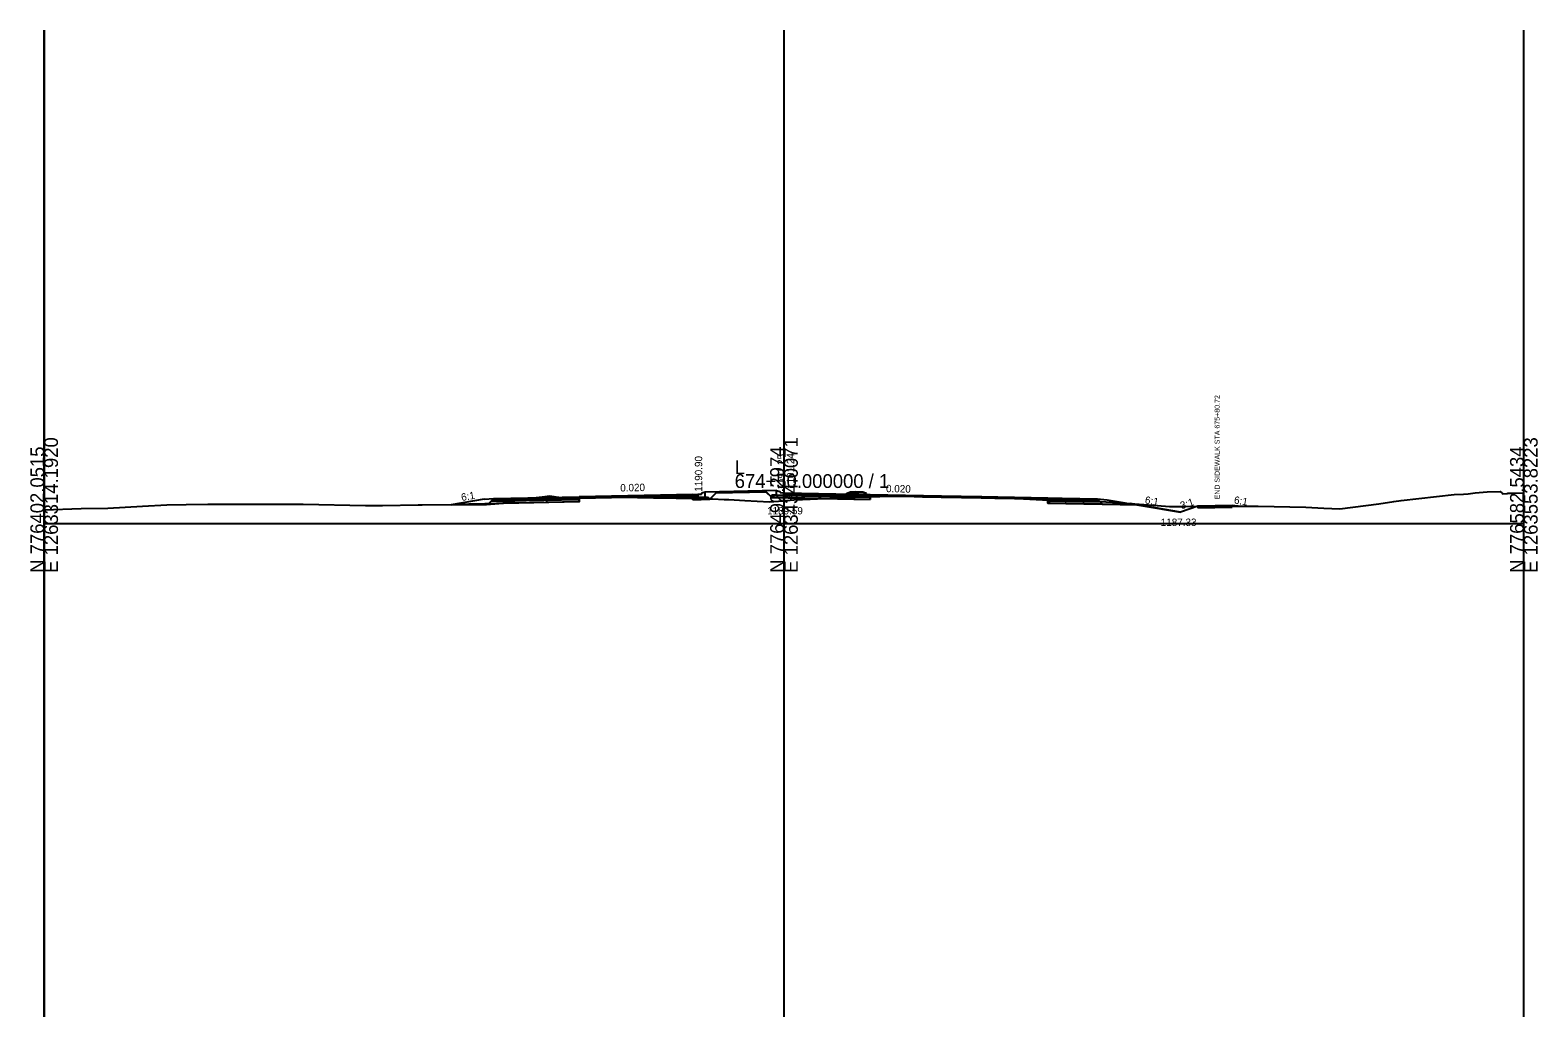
# Model space of a CAD drawing. Extents: x -41 to 1262860, y -100 to 777489.
# Drawn here: x 497.2 to 802.8, y 760 to 960 of the extents above; entities that cross this region are included whole.
import ezdxf

# ---------------------------------------------------------------- set-up
doc = ezdxf.new("R2010")
doc.units = 0
for name, color, linetype in [('Exist Cross Section Cell', 7, 'Continuous'), ('Exist XS Center Line Elevation Label', 7, 'Continuous'), ('Exist XS Ground Line', 7, 'Continuous'), ('Prop CMT Pvmt Concrete', 7, 'Continuous'), ('Prop CMT Pvmt Course 1', 7, 'Continuous'), ('Prop CMT Pvmt Course 4', 7, 'Continuous'), ('Prop CMT Pvmt Surface', 7, 'Continuous'), ('Prop CMT Shld Paved Course 1', 7, 'Continuous'), ('Prop CMT Shld Paved Course 2', 7, 'Continuous'), ('Prop CMT Shld Paved Course 4', 7, 'Continuous'), ('Prop CMT Subgrade Earthwork', 7, 'Continuous'), ('Prop Conc Curb and Gutter', 7, 'Continuous'), ('Prop Conc Island Cover', 7, 'Continuous'), ('Prop XS Ditch Standard Text', 7, 'Continuous'), ('Prop XS Earthwork Shape', 7, 'Continuous'), ('Prop XS Elevation Labels', 7, 'Continuous'), ('Prop XS Exc Vertical Line 1', 7, 'Continuous'), ('Prop XS Exc Vertical Line 2', 7, 'Continuous'), ('Prop XS Exc Vertical Line 3', 7, 'Continuous'), ('Prop XS Finish Grade', 7, 'Continuous'), ('Prop XS Hydro Elevations', 7, 'Continuous'), ('Prop XS SE Text', 7, 'Continuous'), ('Prop XS Side Slope Text', 7, 'Continuous'), ('Scratch_Level_4', 7, 'Continuous'), ('Scratch_Level_6', 7, 'Continuous')]:
    doc.layers.add(name, color=color, linetype=linetype)

msp = doc.modelspace()

# ---------------------------------------------------------------- linework, layer by layer
at = {"layer": 'Exist Cross Section Cell'}
for p, q in [((650, 860), (650, 870)), ((500, 860), (650, 860)), ((650, 860), (800, 860))]:
    msp.add_line(p, q, dxfattribs=at)
at = {"layer": 'Exist XS Ground Line'}
msp.add_lwpolyline([(500, 862.79), (500.03, 862.79), (507.53, 863.01), (512.9, 863.13), (519.95, 863.5), (524.84, 863.75), (528.77, 863.87), (533.18, 863.92), (548.07, 863.95), (551.09, 863.9), (552.54, 863.9), (565.18, 863.68), (568.59, 863.62), (575.86, 863.75), (576.53, 863.76), (576.56, 863.76), (576.67, 863.76), (587.02, 863.82), (589.67, 863.84), (592.15, 864.07), (597.43, 864.93), (598.99, 865.17), (600.42, 865.36), (602.55, 865.6), (604.31, 865.33), (606.22, 864.85), (607.18, 865.08), (608.05, 865.15), (611.41, 865.3), (617.02, 865.31), (623.51, 865.22), (628.16, 865.12), (635.49, 864.98), (637.87, 864.89), (638.84, 864.85), (642.05, 864.65), (647.05, 864.42), (649.74, 864.57), (652, 864.77), (653.51, 864.88), (653.77, 864.89), (664.41, 865.33), (666.01, 865.39), (676.36, 865.62), (678.08, 865.66), (679.35, 865.64), (690.13, 865.46), (692.72, 865.32), (693.38, 865.28), (703.7, 864.7), (705.7, 864.63), (705.97, 864.62), (706.83, 864.58), (708.7, 864.57), (711.21, 864.61), (716.59, 864.3), (725.66, 863.62), (728.13, 863.42), (731.4, 863.45), (736.16, 863.53), (746.13, 863.52), (755.78, 863.3), (759.44, 863.11), (762.68, 862.96), (770.61, 864), (773.62, 864.46), (775.16, 864.67), (785.9, 865.85), (787.78, 865.94), (788.72, 866.04), (790.11, 866.21), (792.59, 866.4), (795.17, 866.52), (795.59, 866.12), (795.67, 866.04), (796.62, 866.1), (796.77, 866.12), (797.92, 866.16), (800, 866.22)], dxfattribs=at)
at = {"layer": 'Prop CMT Pvmt Concrete'}
for p, q in [((733.89, 863.49), (740.85, 863.63)), ((733.89, 863.49), (733.89, 863.16)), ((733.89, 863.16), (740.85, 863.3)), ((740.85, 863.63), (740.85, 863.3))]:
    msp.add_line(p, q, dxfattribs=at)
at = {"layer": 'Prop CMT Pvmt Course 1'}
for p, q in [((631.5, 865.87), (632.5, 865.89)), ((631.5, 865.62), (632.5, 865.64)), ((632.5, 865.64), (632.5, 865.89)), ((650, 866.24), (650, 865.99))]:
    msp.add_line(p, q, dxfattribs=at)
for points in [[(608.5, 865.41), (608.5, 865.16), (631.5, 865.62), (631.5, 865.62), (631.5, 865.87), (631.5, 865.87), (631.5, 865.87), (608.5, 865.41), (608.5, 865.41)], [(703.5, 865.17), (703.5, 864.92), (689.99, 865.19), (689.99, 865.19), (689.99, 865.19), (681.96, 865.35), (681.85, 865.35), (681.85, 865.35), (667.5, 865.64), (667.5, 865.64), (667.5, 865.89), (667.5, 865.89), (667.5, 865.89), (681.85, 865.6), (681.85, 865.6), (681.96, 865.6), (689.99, 865.44), (689.99, 865.44), (689.99, 865.44), (703.5, 865.17), (703.5, 865.17)]]:
    msp.add_lwpolyline(points, dxfattribs=at)
at = {"layer": 'Prop CMT Pvmt Course 4'}
for p, q in [((631.5, 864.83), (631.5, 865.29)), ((667.5, 864.85), (667.5, 865.42)), ((590.58, 864.47), (590.11, 864)), ((608.5, 864.37), (590.11, 864)), ((631.5, 864.83), (634.95, 864.9))]:
    msp.add_line(p, q, dxfattribs=at)
msp.add_lwpolyline([(647.55, 865.25), (667.5, 864.85)], dxfattribs=at)
at = {"layer": 'Prop CMT Pvmt Surface'}
for p, q in [((591.18, 865.06), (608.5, 865.41)), ((608.5, 865.41), (631.5, 865.87)), ((631.5, 865.87), (632.5, 865.89)), ((650, 866.24), (667.5, 865.89)), ((667.5, 865.89), (713.5, 864.97))]:
    msp.add_line(p, q, dxfattribs=at)
at = {"layer": 'Prop CMT Shld Paved Course 1'}
for p, q in [((608.5, 865.16), (590.92, 864.81)), ((601.89, 865.03), (601.89, 865.28)), ((604.5, 865.33), (604.5, 865.33)), ((608.5, 865.41), (608.5, 865.16)), ((608.5, 865.16), (608.5, 865.16)), ((703.73, 865.16), (703.73, 864.91)), ((707.73, 865.08), (707.73, 865.08)), ((591.18, 865.06), (590.92, 864.81)), ((703.5, 864.92), (713.76, 864.71)), ((703.73, 864.91), (703.73, 864.91)), ((713.76, 864.71), (713.5, 864.97))]:
    msp.add_line(p, q, dxfattribs=at)
for points in [[(650, 866.24), (650, 866.24), (667.5, 865.89)], [(650, 865.99), (650, 865.99), (667.5, 865.64)]]:
    msp.add_lwpolyline(points, dxfattribs=at)
at = {"layer": 'Prop CMT Shld Paved Course 2'}
for p, q in [((608.5, 865.16), (611.41, 865.22)), ((611.41, 865.22), (608.5, 865.16)), ((608.5, 865.16), (608.5, 864.83)), ((617.02, 865.33), (611.41, 865.22)), ((611.41, 865.22), (616.04, 865.31)), ((611.41, 865.22), (611.41, 865.22)), ((611.41, 865.22), (611.41, 865.22)), ((611.41, 865.22), (611.41, 865.22)), ((611.41, 865.22), (611.41, 865.22)), ((611.41, 865.22), (611.41, 865.22)), ((616.04, 865.31), (616.04, 865.31)), ((616.04, 865.31), (616.04, 865.31)), ((616.04, 865.31), (617.02, 865.31)), ((623.51, 865.46), (617.02, 865.33)), ((617.02, 865.33), (617.02, 865.33)), ((617.02, 865.31), (617.02, 865.31)), ((617.02, 865.31), (623.51, 865.22)), ((628.16, 865.55), (623.51, 865.46)), ((623.51, 865.22), (625.85, 865.17)), ((625.85, 865.17), (628.16, 865.22)), ((625.85, 865.17), (625.85, 865.17)), ((631.5, 865.62), (628.16, 865.55)), ((628.16, 865.55), (628.16, 865.55)), ((628.16, 865.22), (631.5, 865.29)), ((628.16, 865.22), (628.16, 865.22)), ((631.5, 865.29), (631.5, 865.62)), ((631.5, 865.62), (631.5, 865.62)), ((631.5, 865.62), (631.5, 865.62)), ((631.5, 865.29), (631.5, 865.29)), ((631.51, 865.29), (632.5, 865.31)), ((632.5, 865.64), (632.5, 865.31)), ((650, 865.66), (650, 865.99)), ((667.5, 865.42), (667.5, 865.64)), ((667.5, 865.64), (667.5, 865.64)), ((667.5, 865.64), (667.5, 865.64)), ((667.5, 865.64), (676.36, 865.46)), ((672.58, 865.54), (667.5, 865.42)), ((667.5, 865.42), (667.5, 865.42)), ((676.36, 865.46), (672.58, 865.54)), ((672.58, 865.54), (672.58, 865.54)), ((678.08, 865.43), (676.36, 865.46)), ((676.36, 865.46), (676.36, 865.46)), ((676.36, 865.46), (676.36, 865.46)), ((676.36, 865.46), (678.08, 865.43)), ((679.35, 865.4), (678.08, 865.43)), ((678.08, 865.43), (679.35, 865.4)), ((681.85, 865.35), (679.35, 865.4)), ((679.35, 865.4), (679.35, 865.4)), ((679.35, 865.4), (679.35, 865.4)), ((679.35, 865.4), (681.85, 865.35)), ((681.96, 865.35), (681.85, 865.35)), ((681.85, 865.35), (681.96, 865.35)), ((689.99, 865.19), (681.96, 865.35)), ((681.96, 865.35), (681.96, 865.35)), ((681.96, 865.35), (681.96, 865.35)), ((681.96, 865.35), (689.99, 865.19)), ((690.13, 865.19), (689.99, 865.19)), ((689.99, 865.19), (689.99, 865.19)), ((689.99, 865.19), (689.99, 865.19)), ((689.99, 865.19), (690.13, 865.19)), ((692.72, 865.13), (690.13, 865.19)), ((690.13, 865.19), (690.13, 865.19)), ((690.13, 865.19), (690.13, 865.19)), ((690.13, 865.19), (692.72, 865.13)), ((693.38, 865.12), (692.72, 865.13)), ((692.72, 865.13), (692.72, 865.13)), ((692.72, 865.13), (692.72, 865.13)), ((692.72, 865.13), (693.38, 865.12)), ((697.79, 865.03), (693.38, 865.12)), ((693.38, 865.12), (693.38, 865.12)), ((693.38, 865.12), (693.38, 865.12)), ((693.38, 865.12), (693.38, 865.12)), ((693.38, 865.12), (693.38, 865.12)), ((693.38, 865.12), (703.5, 864.92)), ((608.5, 864.83), (590.58, 864.47)), ((590.58, 864.47), (590.92, 864.81)), ((601.89, 864.69), (601.89, 865.03)), ((603.9, 864.73), (603.9, 864.73)), ((603.9, 864.73), (603.9, 864.73)), ((608.5, 864.83), (608.5, 864.83)), ((703.5, 864.71), (697.79, 865.03)), ((697.79, 865.03), (697.79, 865.03)), ((697.79, 865.03), (697.79, 865.03)), ((703.5, 864.92), (703.5, 864.92)), ((703.5, 864.92), (703.5, 864.92)), ((703.5, 864.92), (703.5, 864.92)), ((703.5, 864.92), (703.5, 864.71)), ((703.5, 864.59), (703.5, 864.71)), ((703.5, 864.71), (703.5, 864.71)), ((703.5, 864.71), (703.5, 864.71)), ((703.5, 864.59), (714.1, 864.37)), ((703.73, 864.91), (703.73, 864.58)), ((703.73, 864.58), (703.73, 864.58)), ((714.1, 864.37), (713.76, 864.71))]:
    msp.add_line(p, q, dxfattribs=at)
msp.add_lwpolyline([(650, 865.66), (667.5, 865.31)], dxfattribs=at)
at = {"layer": 'Prop CMT Shld Paved Course 4'}
for p, q in [((625.85, 865.17), (628.16, 865.12)), ((628.16, 865.12), (631.5, 865.06)), ((632.5, 865.31), (634.5, 865.35)), ((634.5, 865.35), (634.95, 864.9)), ((648, 865.7), (647.55, 865.25)), ((650, 865.66), (648, 865.7)), ((601.89, 864.23), (601.89, 864.69)), ((603.9, 864.73), (603.9, 864.73)), ((608.5, 864.83), (608.5, 864.37)), ((703.5, 864.59), (703.5, 864.13)), ((703.73, 864.58), (703.73, 864.12)), ((703.73, 864.12), (714.8, 863.9)), ((714.56, 863.91), (714.1, 864.37))]:
    msp.add_line(p, q, dxfattribs=at)
at = {"layer": 'Prop CMT Subgrade Earthwork'}
for p, q in [((608.5, 864.37), (608.5, 865.17)), ((634.95, 864.9), (636.45, 866.39)), ((647.55, 865.25), (646.17, 866.63)), ((667.5, 864.85), (647.55, 865.25)), ((667.5, 865.42), (667.5, 864.85)), ((608.5, 864.37), (582.89, 863.85)), ((631.5, 864.83), (631.5, 865.06)), ((634.95, 864.9), (631.5, 864.83)), ((703.5, 864.13), (703.5, 864.71)), ((703.5, 864.13), (721.78, 863.76))]:
    msp.add_line(p, q, dxfattribs=at)
at = {"layer": 'Prop Conc Curb and Gutter'}
for p, q in [((633.19, 865.9), (632.5, 865.89)), ((632.5, 865.89), (632.5, 865.31)), ((632.5, 865.31), (634, 865.34)), ((633.25, 865.98), (633.25, 865.96)), ((634, 866.34), (633.35, 866.12)), ((634, 865.34), (634, 866.34)), ((634, 865.34), (634, 865.34)), ((648.5, 866.69), (649.15, 866.47)), ((648.5, 865.69), (648.5, 866.69)), ((650, 865.66), (648.5, 865.69)), ((649.25, 866.33), (649.25, 866.31)), ((649.31, 866.25), (650, 866.24)), ((650, 865.66), (650, 866.24)), ((662.75, 865.98), (662.76, 866.15)), ((662.75, 865.98), (662.75, 865.98)), ((662.75, 865.98), (662.75, 865.86)), ((664.51, 865.98), (662.75, 865.98)), ((662.75, 865.98), (662.75, 865.98)), ((662.75, 865.86), (662.75, 865.86)), ((662.75, 865.86), (664.51, 865.86)), ((662.76, 866.15), (663.51, 866.4)), ((662.76, 866.15), (662.76, 866.15)), ((663.51, 866.4), (664.51, 866.42)), ((663.51, 866.4), (663.51, 866.4)), ((664.51, 866.42), (664.51, 865.98)), ((664.51, 865.86), (664.51, 865.98)), ((664.51, 865.98), (664.51, 865.98)), ((664.51, 865.86), (664.51, 865.86)), ((664.51, 865.86), (664.51, 865.86)), ((665.99, 866.32), (664.99, 866.34)), ((664.99, 866.34), (664.99, 865.9)), ((666.75, 865.9), (664.99, 865.9)), ((664.99, 865.9), (664.99, 865.78)), ((664.99, 865.9), (664.99, 865.9)), ((664.99, 865.78), (664.99, 865.78)), ((664.99, 865.78), (666.75, 865.78)), ((666.74, 866.07), (665.99, 866.32)), ((665.99, 866.32), (665.99, 866.32)), ((666.75, 865.9), (666.74, 866.07)), ((666.74, 866.07), (666.74, 866.07)), ((666.75, 865.78), (666.75, 865.9)), ((666.75, 865.9), (666.75, 865.9)), ((666.75, 865.9), (666.75, 865.9)), ((666.75, 865.78), (666.75, 865.78)), ((666.75, 865.78), (666.75, 865.78))]:
    msp.add_line(p, q, dxfattribs=at)
for centre, radius, start, end in [((633.19, 865.96), 0.0625, 271.1458, 360), ((633.4, 865.98), 0.146, 108.435, 180), ((649.1, 866.33), 0.146, 0, 71.565), ((649.31, 866.31), 0.0625, 180, 268.8542)]:
    msp.add_arc(centre, radius, start, end, dxfattribs=at)
at = {"layer": 'Prop Conc Island Cover'}
for p, q in [((648.5, 866.69), (634, 866.34)), ((634, 866.07), (634, 866.07)), ((664.51, 866.42), (664.51, 866.17)), ((664.99, 866.34), (664.51, 866.42)), ((664.99, 866.09), (664.51, 866.17)), ((664.99, 866.09), (664.99, 866.34)), ((664.99, 866.34), (664.99, 866.34)), ((664.99, 866.09), (664.99, 866.09))]:
    msp.add_line(p, q, dxfattribs=at)
at = {"layer": 'Prop XS Earthwork Shape'}
for points in [[(602.55, 865.6), (604.31, 865.33), (606.22, 864.85), (607.18, 865.08), (608.05, 865.15), (608.5, 865.17), (608.5, 864.37), (591.7, 864.03), (592.15, 864.07), (597.43, 864.93), (598.99, 865.17), (600.42, 865.36)], [(637.87, 864.89), (638.84, 864.85), (642.05, 864.65), (647.05, 864.42), (649.74, 864.57), (652, 864.77), (653.51, 864.88), (653.77, 864.89), (657.55, 865.05), (647.55, 865.25), (646.41, 866.38), (636.19, 866.14), (635.04, 864.99), (635.49, 864.98)], [(667.5, 864.85), (657.55, 865.05), (664.41, 865.33), (666.01, 865.39), (667.5, 865.42)], [(582.52, 863.79), (587.02, 863.82), (589.67, 863.84), (591.7, 864.03), (590.11, 864), (582.89, 863.85)], [(631.5, 864.83), (631.5, 865.06), (635.04, 864.99), (634.95, 864.9)], [(705.7, 864.63), (705.97, 864.62), (706.83, 864.58), (708.7, 864.57), (711.21, 864.61), (714.02, 864.45), (714.56, 863.91), (703.5, 864.13), (703.5, 864.71), (703.7, 864.7)], [(714.02, 864.45), (716.59, 864.3), (720.15, 864.03), (721.78, 863.76), (714.56, 863.91)], [(733.89, 863.49), (730.39, 862.33), (721.78, 863.76), (720.15, 864.03), (725.66, 863.62), (728.13, 863.42), (731.4, 863.45)], [(740.85, 863.63), (741.35, 863.64), (742.05, 863.52), (736.16, 863.53), (733.89, 863.49)]]:
    msp.add_lwpolyline(points, close=True, dxfattribs=at)
at = {"layer": 'Prop XS Exc Vertical Line 1'}
msp.add_line((500, 760), (500, 960), dxfattribs=at)
at = {"layer": 'Prop XS Exc Vertical Line 2'}
msp.add_line((650, 760), (650, 960), dxfattribs=at)
at = {"layer": 'Prop XS Exc Vertical Line 3'}
msp.add_line((800, 760), (800, 960), dxfattribs=at)
at = {"layer": 'Prop XS Finish Grade'}
for p, q in [((589.18, 864.9), (582.52, 863.79)), ((589.18, 864.9), (591.18, 865.06)), ((591.18, 865.06), (590.11, 864)), ((713.5, 864.97), (715.5, 864.81)), ((713.5, 864.97), (714.56, 863.91)), ((715.5, 864.81), (730.39, 862.33)), ((733.89, 863.49), (730.39, 862.33)), ((740.85, 863.63), (733.89, 863.49)), ((740.85, 863.63), (741.35, 863.64)), ((741.35, 863.64), (742.05, 863.52))]:
    msp.add_line(p, q, dxfattribs=at)
at = {"layer": 'Scratch_Level_4'}
msp.add_line((800, 760), (800, 960), dxfattribs=at)
at = {"layer": 'Scratch_Level_6'}
msp.add_line((500, 960), (500, 760), dxfattribs=at)

# ---------------------------------------------------------------- texts
at = {"layer": 'Exist Cross Section Cell'}
for s, p in [('E 1263314.1920', (502.8, 850)), ('E 1263553.8223', (802.8, 850)), ('N 776402.0515', (500, 850)), ('N 776492.2974', (650, 850)), ('E 1263434.0071', (652.8, 850)), ('N 776582.5434', (800, 850))]:
    msp.add_text(s, height=2.8, rotation=90, dxfattribs=at).set_placement(p)
for s, p in [('L', (640, 870)), ('674+50.000000 / 1', (640, 867.2))]:
    msp.add_text(s, height=2.8, dxfattribs=at).set_placement(p)
at = {"layer": 'Exist XS Center Line Elevation Label'}
msp.add_text('1189.59', height=1.5, dxfattribs=at).set_placement((646.57, 861.84))
at = {"layer": 'Prop XS Ditch Standard Text'}
msp.add_text('1187.33', height=1.5, dxfattribs=at).set_placement((726.38, 859.5))
at = {"layer": 'Prop XS Elevation Labels'}
for s, p in [('1190.90', (633.42, 866.43)), ('1191.25', (650.18, 866.85))]:
    msp.add_text(s, height=1.5, rotation=90, dxfattribs=at).set_placement(p)
at = {"layer": 'Prop XS Hydro Elevations'}
for s, height, p in [('END SIDEWALK STA 675+80.72', 1.0331, (738.34, 864.89)), ('1191.24', 1.5, (652.07, 867.01))]:
    msp.add_text(s, height=height, rotation=90, dxfattribs=at).set_placement(p)
at = {"layer": 'Prop XS SE Text'}
for rotation, p in [(1.1458, (616.81, 866.48)), (358.8542, (670.67, 866.35))]:
    msp.add_text('0.020', height=1.5, rotation=rotation, dxfattribs=at).set_placement(p)
at = {"layer": 'Prop XS Side Slope Text'}
for s, rotation, p in [('6:1', 9.4623, (584.67, 864.56)), ('6:1', 350.5377, (723.09, 864.08)), ('6:1', 350.5377, (741.16, 864.08)), ('3:1', 18.4349, (730.62, 862.87))]:
    msp.add_text(s, height=1.5, rotation=rotation, dxfattribs=at).set_placement(p)

doc.saveas('drawing.dxf')
